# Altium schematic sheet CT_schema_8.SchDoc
size 274 x 160 mm
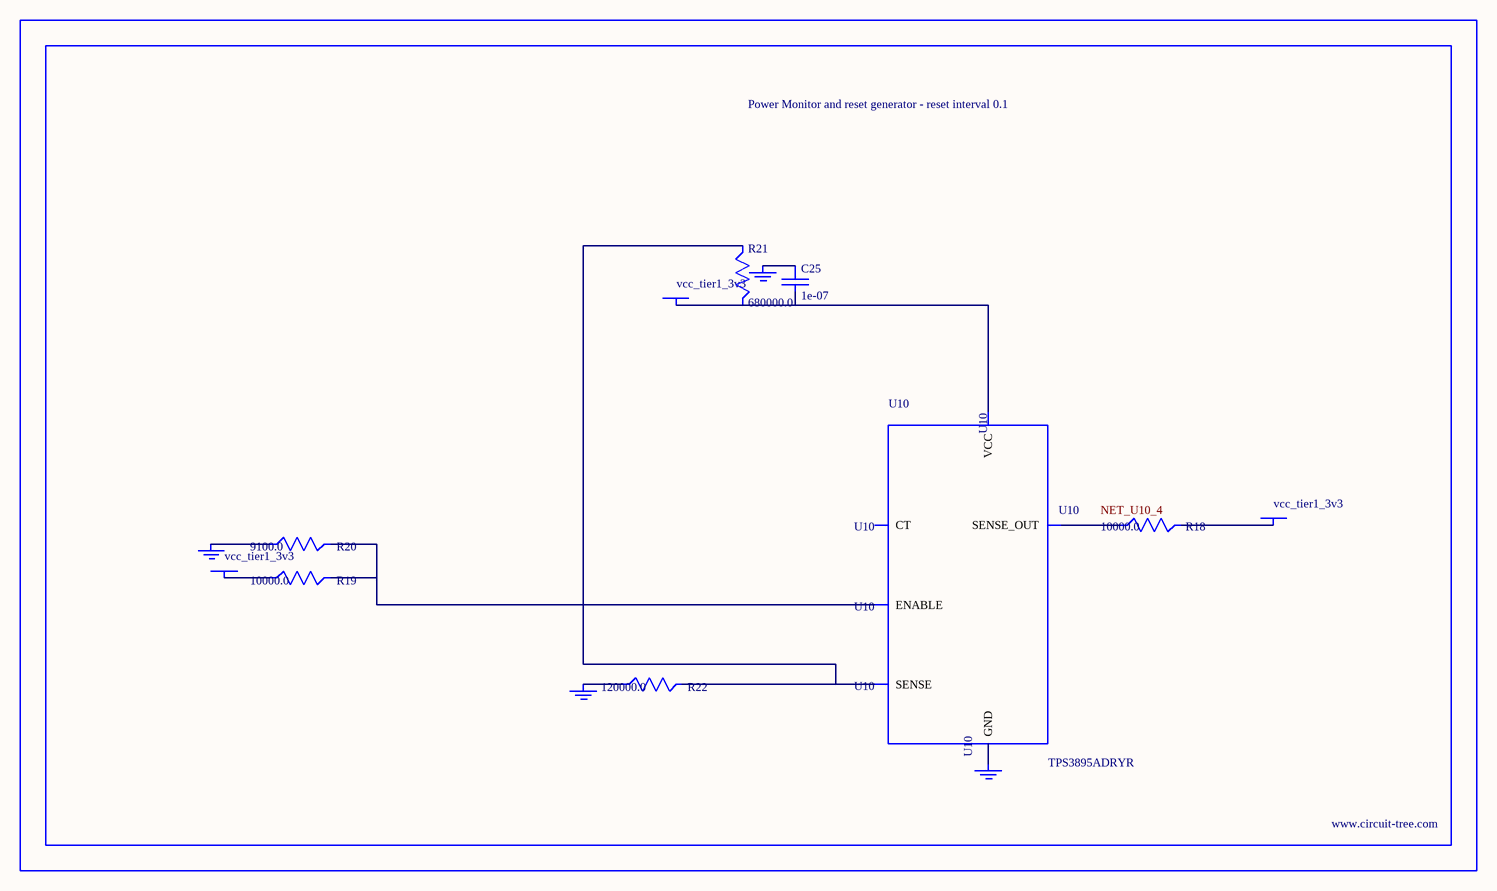
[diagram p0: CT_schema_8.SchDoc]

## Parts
BORDER7  (no value)
C25  1e-07  [C0402]
GND_INSTANCE_7_0  (no value)
GND_INSTANCE_7_1  (no value)
GND_INSTANCE_7_2  (no value)
GND_INSTANCE_7_3  (no value)
POWER_INSTANCE_7_0  vcc_tier1_3v3
POWER_INSTANCE_7_1  vcc_tier1_3v3
POWER_INSTANCE_7_2  vcc_tier1_3v3
R18  10000.0  [R0603]
R19  10000.0  [R0603]
R20  9100.0  [R0603]
R21  680000.0  [R0603]
R22  120000.0  [R0603]
U10  TPS3895ADRYR  [SON-6]

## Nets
NetC25_1: C25.1 GND_INSTANCE_7_2.0(GND)
NetC25_2: C25.2 POWER_INSTANCE_7_2.0(PWR) R21.2 U10.6(VCC)
NetGND_INSTANCE_7_0_0: GND_INSTANCE_7_0.0(GND) R20.1
NetGND_INSTANCE_7_1_0: GND_INSTANCE_7_1.0(GND) R22.1
NetGND_INSTANCE_7_3_0: GND_INSTANCE_7_3.0(GND) U10.2(GND)
NetPOWER_INSTANCE_7_0_0: POWER_INSTANCE_7_0.0(PWR) R19.1
NetPOWER_INSTANCE_7_1_0: POWER_INSTANCE_7_1.0(PWR) R18.2
NetR18_1: R18.1 U10.4(SENSE_OUT)
NetR19_2: R19.2 R20.2 U10.1(ENABLE)
NetR21_1: R21.1 R22.2 U10.3(SENSE)

Not connected (* = marked no-connect by the designer): U10 5(CT)

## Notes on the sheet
- Labels drawn without touching a wire or pin: NET_U10_4

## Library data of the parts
BORDER7 = BORDER_PAGE7
C25 = C0402C104K3RACTU
GND_INSTANCE_7_0-GND_INSTANCE_7_3 = GND
POWER_INSTANCE_7_0-POWER_INSTANCE_7_2 = PWR
R18 R19 = RC0603JR-0710KL
R20 = RC0603JR-079K1L
R21 = RC0603JR-07680KL
R22 = RC0603JR-07120KL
